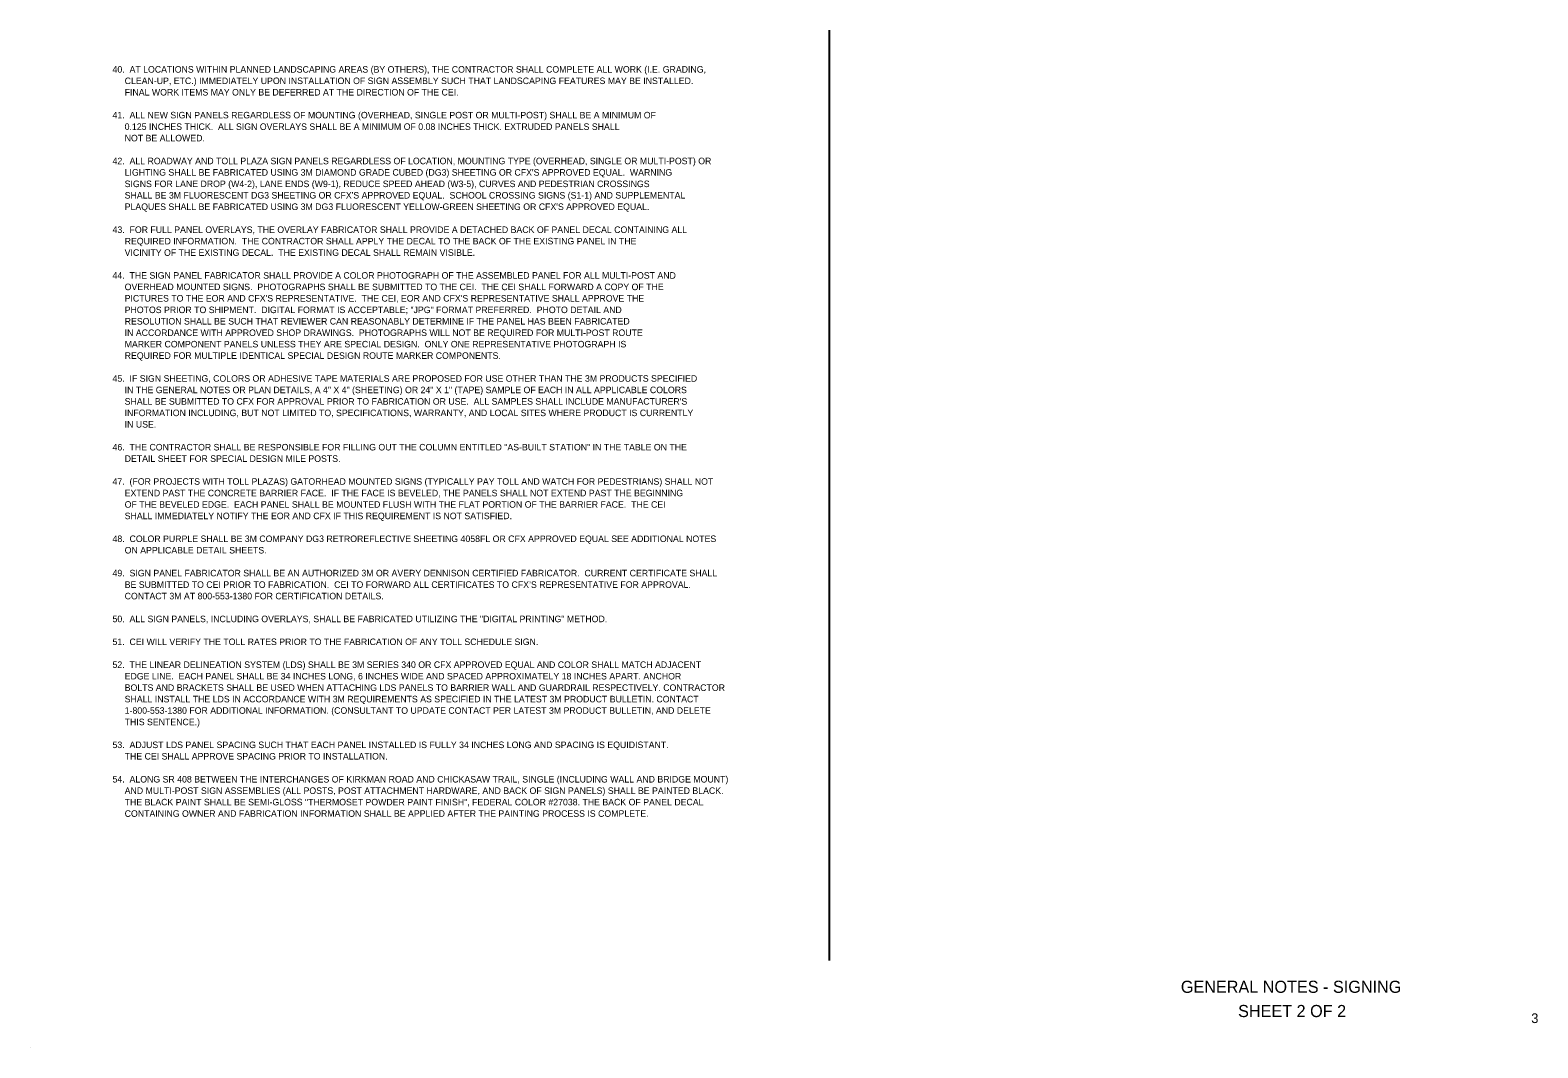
# Model space of a CAD drawing. Extents: x 2479953 to 2481508, y 3678869 to 3679919.
import ezdxf

# ---------------------------------------------------------------- set-up
doc = ezdxf.new("R2010")
doc.units = 0
for name, color, linetype in [('AdhocPoint_dp', 7, 'Continuous'), ('NonPlottingEle_dp', 7, 'Continuous'), ('TextLabel', 7, 'Continuous'), ('TextMisc', 7, 'Continuous'), ('TextShtNo', 7, 'Continuous')]:
    doc.layers.add(name, color=color, linetype=linetype)

msp = doc.modelspace()

# ---------------------------------------------------------------- linework, layer by layer
at = {"layer": 'AdhocPoint_dp'}
msp.add_line((2479952.6, 3678869), (2479952.6, 3678869), dxfattribs=at)
at = {"layer": 'NonPlottingEle_dp'}
msp.add_line((2480777.6, 3678959), (2480777.6, 3679919), dxfattribs=at)

# ---------------------------------------------------------------- texts
at = {"layer": 'TextLabel'}
for s, p in [('40.  AT LOCATIONS WITHIN PLANNED LANDSCAPING AREAS (BY OTHERS), THE CONTRACTOR SHALL COMPLETE ALL WORK (I.E. GRADING,', (2480037.6, 3679875.2)), ('     CLEAN-UP, ETC.) IMMEDIATELY UPON INSTALLATION OF SIGN ASSEMBLY SUCH THAT LANDSCAPING FEATURES MAY BE INSTALLED.', (2480037.6, 3679863.4)), ('     FINAL WORK ITEMS MAY ONLY BE DEFERRED AT THE DIRECTION OF THE CEI.', (2480037.6, 3679851.6)), ('41.  ALL NEW SIGN PANELS REGARDLESS OF MOUNTING (OVERHEAD, SINGLE POST OR MULTI-POST) SHALL BE A MINIMUM OF', (2480037.6, 3679828)), ('     0.125 INCHES THICK.  ALL SIGN OVERLAYS SHALL BE A MINIMUM OF 0.08 INCHES THICK. EXTRUDED PANELS SHALL', (2480037.6, 3679816.1)), ('     NOT BE ALLOWED.', (2480037.6, 3679804.3)), ('42.  ALL ROADWAY AND TOLL PLAZA SIGN PANELS REGARDLESS OF LOCATION, MOUNTING TYPE (OVERHEAD, SINGLE OR MULTI-POST) OR', (2480037.6, 3679780.7)), ("     LIGHTING SHALL BE FABRICATED USING 3M DIAMOND GRADE CUBED (DG3) SHEETING OR CFX'S APPROVED EQUAL.  WARNING", (2480037.6, 3679768.9)), ('     SIGNS FOR LANE DROP (W4-2), LANE ENDS (W9-1), REDUCE SPEED AHEAD (W3-5), CURVES AND PEDESTRIAN CROSSINGS', (2480037.6, 3679757.1)), ("     SHALL BE 3M FLUORESCENT DG3 SHEETING OR CFX'S APPROVED EQUAL.  SCHOOL CROSSING SIGNS (S1-1) AND SUPPLEMENTAL", (2480037.6, 3679745.3)), ("     PLAQUES SHALL BE FABRICATED USING 3M DG3 FLUORESCENT YELLOW-GREEN SHEETING OR CFX'S APPROVED EQUAL.", (2480037.6, 3679733.5)), ('43.  FOR FULL PANEL OVERLAYS, THE OVERLAY FABRICATOR SHALL PROVIDE A DETACHED BACK OF PANEL DECAL CONTAINING ALL', (2480037.6, 3679709.8)), ('     REQUIRED INFORMATION.  THE CONTRACTOR SHALL APPLY THE DECAL TO THE BACK OF THE EXISTING PANEL IN THE', (2480037.6, 3679698)), ('     VICINITY OF THE EXISTING DECAL.  THE EXISTING DECAL SHALL REMAIN VISIBLE.', (2480037.6, 3679686.2)), ('44.  THE SIGN PANEL FABRICATOR SHALL PROVIDE A COLOR PHOTOGRAPH OF THE ASSEMBLED PANEL FOR ALL MULTI-POST AND', (2480037.6, 3679662.6)), ('     OVERHEAD MOUNTED SIGNS.  PHOTOGRAPHS SHALL BE SUBMITTED TO THE CEI.  THE CEI SHALL FORWARD A COPY OF THE', (2480037.6, 3679650.8)), ("     PICTURES TO THE EOR AND CFX'S REPRESENTATIVE.  THE CEI, EOR AND CFX'S REPRESENTATIVE SHALL APPROVE THE", (2480037.6, 3679639)), ('     PHOTOS PRIOR TO SHIPMENT.  DIGITAL FORMAT IS ACCEPTABLE; "JPG" FORMAT PREFERRED.  PHOTO DETAIL AND', (2480037.6, 3679627.1)), ('     RESOLUTION SHALL BE SUCH THAT REVIEWER CAN REASONABLY DETERMINE IF THE PANEL HAS BEEN FABRICATED', (2480037.6, 3679615.3)), ('     IN ACCORDANCE WITH APPROVED SHOP DRAWINGS.  PHOTOGRAPHS WILL NOT BE REQUIRED FOR MULTI-POST ROUTE', (2480037.6, 3679603.5)), ('     MARKER COMPONENT PANELS UNLESS THEY ARE SPECIAL DESIGN.  ONLY ONE REPRESENTATIVE PHOTOGRAPH IS', (2480037.6, 3679591.7)), ('     REQUIRED FOR MULTIPLE IDENTICAL SPECIAL DESIGN ROUTE MARKER COMPONENTS.', (2480037.6, 3679579.9)), ('45.  IF SIGN SHEETING, COLORS OR ADHESIVE TAPE MATERIALS ARE PROPOSED FOR USE OTHER THAN THE 3M PRODUCTS SPECIFIED', (2480037.6, 3679556.3)), ("     SHALL BE SUBMITTED TO CFX FOR APPROVAL PRIOR TO FABRICATION OR USE.  ALL SAMPLES SHALL INCLUDE MANUFACTURER'S", (2480037.6, 3679532.6)), ('     IN THE GENERAL NOTES OR PLAN DETAILS, A 4" X 4" (SHEETING) OR 24" X 1" (TAPE) SAMPLE OF EACH IN ALL APPLICABLE COLORS', (2480037.6, 3679544.5)), ('     INFORMATION INCLUDING, BUT NOT LIMITED TO, SPECIFICATIONS, WARRANTY, AND LOCAL SITES WHERE PRODUCT IS CURRENTLY', (2480037.6, 3679520.8)), ('     IN USE.', (2480037.6, 3679509)), ('46.  THE CONTRACTOR SHALL BE RESPONSIBLE FOR FILLING OUT THE COLUMN ENTITLED "AS-BUILT STATION" IN THE TABLE ON THE ', (2480037.6, 3679485.4)), ('     DETAIL SHEET FOR SPECIAL DESIGN MILE POSTS.', (2480037.6, 3679473.6)), ('47.  (FOR PROJECTS WITH TOLL PLAZAS) GATORHEAD MOUNTED SIGNS (TYPICALLY PAY TOLL AND WATCH FOR PEDESTRIANS) SHALL NOT', (2480037.6, 3679450)), ('     OF THE BEVELED EDGE.  EACH PANEL SHALL BE MOUNTED FLUSH WITH THE FLAT PORTION OF THE BARRIER FACE.  THE CEI', (2480037.6, 3679426.3)), ('     EXTEND PAST THE CONCRETE BARRIER FACE.  IF THE FACE IS BEVELED, THE PANELS SHALL NOT EXTEND PAST THE BEGINNING', (2480037.6, 3679438.1)), ('     SHALL IMMEDIATELY NOTIFY THE EOR AND CFX IF THIS REQUIREMENT IS NOT SATISFIED.', (2480037.6, 3679414.5)), ('48.  COLOR PURPLE SHALL BE 3M COMPANY DG3 RETROREFLECTIVE SHEETING 4058FL OR CFX APPROVED EQUAL SEE ADDITIONAL NOTES', (2480037.6, 3679390.9)), ('     ON APPLICABLE DETAIL SHEETS.', (2480037.6, 3679379.1)), ('49.  SIGN PANEL FABRICATOR SHALL BE AN AUTHORIZED 3M OR AVERY DENNISON CERTIFIED FABRICATOR.  CURRENT CERTIFICATE SHALL', (2480037.6, 3679355.5)), ('     CONTACT 3M AT 800-553-1380 FOR CERTIFICATION DETAILS.', (2480037.6, 3679331.8)), ('     BE SUBMITTED TO CEI PRIOR TO FABRICATION.  CEI TO FORWARD ALL CERTIFICATES TO CFX’S REPRESENTATIVE FOR APPROVAL.  ', (2480037.6, 3679343.6)), ('50.  ALL SIGN PANELS, INCLUDING OVERLAYS, SHALL BE FABRICATED UTILIZING THE "DIGITAL PRINTING" METHOD.', (2480037.6, 3679308.2)), ('51.  CEI WILL VERIFY THE TOLL RATES PRIOR TO THE FABRICATION OF ANY TOLL SCHEDULE SIGN.', (2480037.6, 3679284.6)), ('52.  THE LINEAR DELINEATION SYSTEM (LDS) SHALL BE 3M SERIES 340 OR CFX APPROVED EQUAL AND COLOR SHALL MATCH ADJACENT ', (2480037.6, 3679261)), ('     EDGE LINE.  EACH PANEL SHALL BE 34 INCHES LONG, 6 INCHES WIDE AND SPACED APPROXIMATELY 18 INCHES APART. ANCHOR ', (2480037.6, 3679249.1)), ('     BOLTS AND BRACKETS SHALL BE USED WHEN ATTACHING LDS PANELS TO BARRIER WALL AND GUARDRAIL RESPECTIVELY. CONTRACTOR ', (2480037.6, 3679237.3)), ('     SHALL INSTALL THE LDS IN ACCORDANCE WITH 3M REQUIREMENTS AS SPECIFIED IN THE LATEST 3M PRODUCT BULLETIN. CONTACT ', (2480037.6, 3679225.5)), ('     1-800-553-1380 FOR ADDITIONAL INFORMATION. (CONSULTANT TO UPDATE CONTACT PER LATEST 3M PRODUCT BULLETIN, AND DELETE ', (2480037.6, 3679213.7)), ('     THIS SENTENCE.)', (2480037.6, 3679201.9)), ('53.  ADJUST LDS PANEL SPACING SUCH THAT EACH PANEL INSTALLED IS FULLY 34 INCHES LONG AND SPACING IS EQUIDISTANT.', (2480037.6, 3679178.3)), ('     THE CEI SHALL APPROVE SPACING PRIOR TO INSTALLATION.', (2480037.6, 3679166.5)), ('54.  ALONG SR 408 BETWEEN THE INTERCHANGES OF KIRKMAN ROAD AND CHICKASAW TRAIL, SINGLE (INCLUDING WALL AND BRIDGE MOUNT) ', (2480037.6, 3679142.8)), ('     AND MULTI-POST SIGN ASSEMBLIES (ALL POSTS, POST ATTACHMENT HARDWARE, AND BACK OF SIGN PANELS) SHALL BE PAINTED BLACK.', (2480037.6, 3679131)), ('     THE BLACK PAINT SHALL BE SEMI-GLOSS "THERMOSET POWDER PAINT FINISH", FEDERAL COLOR #27038. THE BACK OF PANEL DECAL', (2480037.6, 3679119.2)), ('     CONTAINING OWNER AND FABRICATION INFORMATION SHALL BE APPLIED AFTER THE PAINTING PROCESS IS COMPLETE.', (2480037.6, 3679107.4))]:
    msp.add_text(s, height=6.75, dxfattribs=at).set_placement(p)
at = {"layer": 'TextMisc'}
for s, p in [('GENERAL NOTES - SIGNING ', (2481140, 3678925.8)), ('      SHEET 2 OF 2      ', (2481171.2, 3678900.8))]:
    msp.add_text(s, height=12.5, rotation=360, dxfattribs=at).set_placement(p)
at = {"layer": 'TextShtNo'}
msp.add_text('  3  ', height=10, rotation=360, dxfattribs=at).set_placement((2481494.1, 3678894.6))

doc.saveas('drawing.dxf')
